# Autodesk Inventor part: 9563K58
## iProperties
Created: 2005-06
Part Number: 9563K58
Document SubType Name: Modeling
Designer: HalG
Manufacturer: Standard
Standards Organization: Custom
Material: Steel, Mild
Description: Finishing Plug, 23/32 Head Dia, 9/16 Mtg Hole, Steel, Nickel Plated Finish
Author: HalG
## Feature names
1. Revolution1
2. Extrusion1
3. Circular Pattern1
